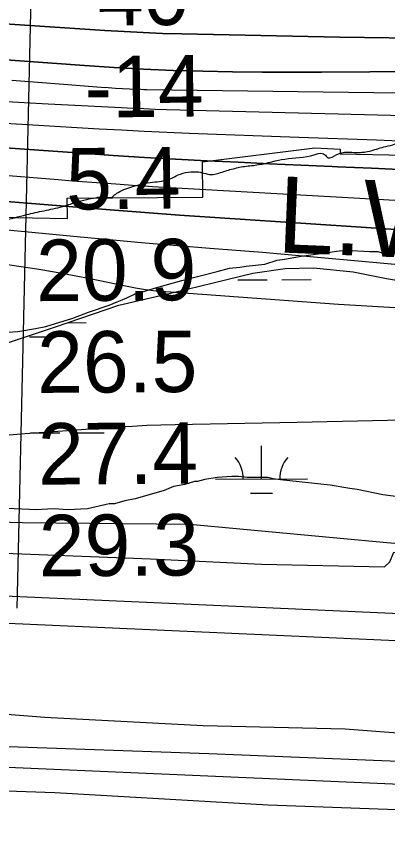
# Model space of a CAD drawing. Extents: x 3329297 to 3367176, y 649250 to 674653.
# Drawn here: x 3334898 to 3335302, y 657903 to 658801 of the extents above; entities that cross this region are included whole.
import ezdxf

# ---------------------------------------------------------------- set-up
doc = ezdxf.new("R2010")
doc.units = 0
for name, color, linetype in [('V-LEVE-TOET', 7, 'Continuous'), ('V-RIVR-EDGE', 7, 'Continuous'), ('V-RIVR-RANG', 7, 'Continuous'), ('V-ROAD-CNTR', 7, 'Continuous'), ('V-RRAP-RVMT', 7, 'Continuous'), ('V-SITE-VEGE', 7, 'Continuous'), ('V-SURV-LINE', 7, 'Continuous'), ('V-TOPO-DPTH', 7, 'Continuous'), ('V-TOPO-MAJR', 7, 'Continuous'), ('V-TOPO-MINR', 7, 'Continuous'), ('V-TOPO-SHOR', 7, 'Continuous'), ('V-TOPO-WATR', 7, 'Continuous'), ('V-TOPO-WATR-IDEN', 7, 'Continuous'), ('V-WETL-SWMP', 7, 'Continuous')]:
    doc.layers.add(name, color=color, linetype=linetype)

msp = doc.modelspace()

# ---------------------------------------------------------------- linework, layer by layer
at = {"layer": 'V-LEVE-TOET'}
for points in [[(3333424.63, 658284.08), (3333476.81, 658281.19), (3333749.42, 658272.3), (3333948.01, 658262.86), (3334211.25, 658250.73), (3334419.86, 658241.85), (3334597.8, 658233.97), (3334838.33, 658218.08), (3335044.27, 658209.9), (3335164.9, 658203.95), (3335298.89, 658201.2), (3335304.94, 658206.46), (3335309.06, 658217.09), (3335518.27, 658202.87)], [(3335958.07, 657989.51), (3335776.1, 657994.77), (3335588.15, 658002.1), (3335408.9, 658012.67), (3335256.34, 658024.29), (3335101.69, 658027.93), (3334929.09, 658037.09), (3334818.5, 658045.6), (3334667.9, 658053.86), (3334510.63, 658061.53), (3334345.37, 658071.29), (3334170.71, 658074.47), (3334012.75, 658080.15), (3333856.17, 658090.48), (3333698.22, 658097.48), (3333552.93, 658103.03), (3333424.89, 658106.3)]]:
    msp.add_lwpolyline(points, dxfattribs=at)
at = {"layer": 'V-RIVR-EDGE'}
msp.add_spline([(3333424.05, 658724.7), (3333474.73, 658717.46), (3333489.07, 658715.87), (3333512.33, 658713.49), (3333530.18, 658715), (3333538.71, 658715.36), (3333547.24, 658714.57), (3333557.71, 658715.7), (3333586.02, 658716.41), (3333612.01, 658718.28), (3333629.86, 658722.12), (3333637.62, 658724.42), (3333647.31, 658724.01), (3333663.6, 658721.26), (3333682.21, 658720.82), (3333707.8, 658719.6), (3333729.52, 658719.93), (3333747.37, 658722.99), (3333760.94, 658721.79), (3333772.95, 658719.82), (3333786.14, 658719.4), (3333801.65, 658718.98), (3333815.21, 658714.68), (3333829.55, 658712.32), (3333853.98, 658710.7), (3333881.51, 658709.09), (3333919.9, 658708.21), (3333933.09, 658708.96), (3333955.19, 658706.58), (3333979.61, 658702.64), (3333997.44, 658699.49), (3334008.3, 658700.63), (3334035.82, 658696.29), (3334058.31, 658693.91), (3334066.07, 658695.06), (3334072.66, 658693.49), (3334092.04, 658688.79), (3334109.87, 658687.19), (3334133.13, 658684.42), (3334151.35, 658681.27), (3334164.92, 658679.69), (3334190.9, 658677.68), (3334204.86, 658676.49), (3334218.42, 658674.13), (3334220.76, 658676.45), (3334226.96, 658676.82), (3334231.62, 658676.81), (3334233.55, 658674.09), (3334237.81, 658672.91), (3334253.71, 658672.87), (3334313.8, 658663.03), (3334340.55, 658660.25), (3334380.48, 658654.72), (3334411.48, 658646.11), (3334421.17, 658643.76), (3334440.16, 658640.23), (3334471.95, 658635.49), (3334501.03, 658634.26), (3334507.24, 658634.24), (3334509.17, 658631.91), (3334513.05, 658629.96), (3334528.94, 658626.05), (3334571.2, 658623.23), (3334582.83, 658621.65), (3334608.04, 658620.81), (3334615.79, 658620.01), (3334621.6, 658617.28), (3334633.23, 658614.93), (3334639.05, 658615.3), (3334646.41, 658615.28), (3334654.94, 658613.71), (3334657.65, 658610.6), (3334668.89, 658607.86), (3334697.18, 658600.03), (3334721.99, 658596.87), (3334746.41, 658594.1), (3334774.71, 658589.76), (3334788.29, 658590.11), (3334793.72, 658591.26), (3334803.41, 658590.85), (3334809.62, 658589.67), (3334816.59, 658585.78), (3334828.61, 658584.97), (3334856.12, 658577.92), (3334862.33, 658577.52), (3334871.63, 658577.89), (3334882.88, 658579.02), (3334909.27, 658585.16), (3334928.28, 658589.38), (3334948.46, 658593.98), (3334962.04, 658598.22), (3334974.85, 658601.67), (3334984.55, 658603.59), (3334993.47, 658604.73), (3335001.61, 658603.94), (3335003.94, 658605.48), (3335009, 658609.35), (3335017.54, 658613.2), (3335043.92, 658620.12), (3335064.1, 658623.56), (3335076.91, 658629.34), (3335088.16, 658631.64), (3335096.31, 658631.62), (3335112.59, 658628.87), (3335118.8, 658630.4), (3335132.38, 658634.64), (3335146.74, 658637.7), (3335161.86, 658639.6), (3335190.58, 658645.74), (3335222.39, 658650.31), (3335231.31, 658651.84), (3335233.64, 658650.67), (3335237.5, 658647.17), (3335247.21, 658650.64), (3335268.93, 658652.91), (3335284.45, 658654.81), (3335300.36, 658659.43), (3335310.45, 658662.12), (3335317.05, 658665.98), (3335327.52, 658665.95), (3335337.6, 658665.54), (3335348.45, 658660.86), (3335353.87, 658658.91), (3335358.52, 658656.96), (3335366.28, 658656.94), (3335378.3, 658655.75), (3335387.6, 658654.95), (3335410.48, 658652.18), (3335422.11, 658652.15), (3335445.77, 658654.8), (3335459.34, 658653.99), (3335474.47, 658652.79), (3335498.1, 658645.75), (3335522.12, 658635.22), (3335524.06, 658634.83), (3335528.73, 658639.86), (3335535.32, 658639.07), (3335541.51, 658635.18), (3335544.99, 658629.74), (3335552.73, 658625.45), (3335563.59, 658624.26), (3335571.34, 658623.47), (3335598.49, 658623.79), (3335622.54, 658624.12), (3335648.9, 658622.5), (3335687.66, 658613.87), (3335732.61, 658599.03), (3335763.22, 658587.32), (3335768.26, 658588.08), (3335771.74, 658585.36), (3335791.88, 658574.06), (3335801.19, 658573.26), (3335807.78, 658573.63), (3335822.89, 658566.23), (3335836.83, 658560.38), (3335873.65, 658551.75), (3335894.2, 658547.82), (3335916.31, 658549.32), (3335929.5, 658552), (3335949.67, 658554.28), (3335958.59, 658554.26), (3335962.85, 658550.76), (3335976.4, 658544.91), (3335989.19, 658542.16), (3335995.01, 658539.82), (3336014.78, 658538.99), (3336032.61, 658534.68), (3336045.79, 658533.1), (3336066.73, 658532.27), (3336083.03, 658535.33), (3336086.53, 658539.2), (3336089.26, 658545.79), (3336091.2, 658548.11), (3336096.25, 658548.88), (3336104.78, 658549.24), (3336126.11, 658548.8), (3336150.54, 658550.29), (3336176.53, 658551.39), (3336187.39, 658554.47), (3336195.94, 658559.49), (3336201.75, 658559.47), (3336210.28, 658556.35), (3336221.52, 658556.71), (3336235.1, 658556.68), (3336248.28, 658557.03), (3336254.1, 658558.57), (3336264.96, 658558.54), (3336271.16, 658553.48), (3336276.57, 658548.82), (3336283.56, 658550.74), (3336285.51, 658553.84), (3336288.62, 658557.71), (3336294.05, 658559.24), (3336313.06, 658561.14), (3336342.15, 658562.62), (3336356.5, 658564.91), (3336366.2, 658566.05), (3336374.35, 658568.35), (3336386.76, 658568.32), (3336402.66, 658568.67), (3336427.86, 658567.83), (3336436.01, 658568.2), (3336451.14, 658570.1), (3336484.9, 658577.78), (3336508.56, 658580.82), (3336517.88, 658587.39), (3336522.54, 658588.15), (3336524.87, 658591.25), (3336527.2, 658593.18), (3336531.86, 658593.17), (3336535.73, 658591.61), (3336537.28, 658588.89), (3336543.87, 658588.88), (3336562.87, 658589.6), (3336584.21, 658591.49), (3336614.46, 658594.13), (3336646.27, 658597.15), (3336666.43, 658596.72), (3336695.13, 658594.32), (3336705.21, 658594.29), (3336734.29, 658593.45), (3336750.58, 658593.02), (3336760.27, 658593.77), (3336768.41, 658592.2), (3336776.93, 658585.97), (3336785.46, 658584.01), (3336796.7, 658582.43), (3336838.19, 658582.33), (3336859.52, 658579.18), (3336880.83, 658572.53), (3336893.24, 658572.5), (3336911.08, 658573.62), (3336926.59, 658573.58), (3336945.21, 658575.47), (3336951.81, 658578.56), (3336960.34, 658578.54), (3336969.64, 658575.8), (3336985.16, 658578.09), (3336999.12, 658578.05), (3337015.8, 658580.34), (3337041.02, 658583.77), (3337061.58, 658586.43), (3337080.98, 658591.43), (3337113.57, 658597.94), (3337142.28, 658602.91), (3337169.45, 658609.43), (3337200.49, 658615.56), (3337235.01, 658620.13), (3337281.96, 658628.93), (3337309.9, 658636.23), (3337337.07, 658645.86), (3337357.25, 658651.63), (3337365.81, 658662.85), (3337368.54, 658669.05), (3337372.81, 658672.53), (3337380.58, 658677.16), (3337399.6, 658684.49), (3337429.1, 658696.82), (3337439.2, 658702.23), (3337449.3, 658709.18), (3337462.89, 658715.35), (3337480.74, 658722.29), (3337488.89, 658723.82), (3337511.41, 658733.85), (3337537.8, 658741.93), (3337559.14, 658747.69), (3337587.46, 658752.27), (3337604.53, 658754.95), (3337622.76, 658756.84), (3337625.48, 658758.39), (3337630.53, 658759.15), (3337640.61, 658759.12), (3337650.68, 658756), (3337655.34, 658755.98), (3337674.74, 658761.37), (3337711.6, 658769.03), (3337723.24, 658772.88), (3337734.87, 658769.75), (3337742.62, 658765.85), (3337750.37, 658765.06), (3337764.33, 658765.41), (3337778.69, 658768.87), (3337789.55, 658769.23), (3337800.81, 658775.02), (3337814.78, 658776.92), (3337832.62, 658779.59), (3337848.13, 658779.94), (3337861.32, 658778.74), (3337867.13, 658775.24), (3337871.01, 658777.17), (3337873.73, 658779.1), (3337884.2, 658779.46), (3337903.6, 658784.46), (3337929.32, 658794.23)], degree=3, dxfattribs=at)
at = {"layer": 'V-RIVR-RANG'}
msp.add_line((3334898.97, 658156.31), (3334925.65, 659316), dxfattribs=at)
at = {"layer": 'V-ROAD-CNTR'}
msp.add_lwpolyline([(3333422.61, 658046.57), (3335843.92, 657941.23)], dxfattribs=at)
at = {"layer": 'V-RRAP-RVMT'}
for p, q in [((3335100.89, 658642.72), (3335222.97, 658658.04)), ((3335222.97, 658658.04), (3335250.86, 658656.35)), ((3335250.86, 658656.35), (3335250.88, 658651.39)), ((3335250.88, 658651.39), (3335321.35, 658650.04)), ((3335101.17, 658604.09), (3335100.89, 658642.72)), ((3334953.62, 658602.95), (3335101.17, 658604.09)), ((3334953.71, 658580.71), (3334953.62, 658602.95)), ((3334797.66, 658583.85), (3334953.71, 658580.71))]:
    msp.add_line(p, q, dxfattribs=at)
at = {"layer": 'V-SITE-VEGE'}
for points in [[(3335116.74, 658523.27), (3335130.3, 658526.59), (3335141.59, 658527.67), (3335148.37, 658528.77), (3335168.7, 658530.93), (3335182.26, 658535.38), (3335190.17, 658536.47), (3335208.24, 658539.77), (3335239.87, 658544.13), (3335246.64, 658545.22), (3335256.81, 658546.3), (3335282.76, 658545.05), (3335291.79, 658545.01), (3335298.55, 658542.72), (3335306.45, 658541.55)], [(3334865.86, 658455.62), (3334899.73, 658457.72), (3334918.93, 658461.02), (3334930.23, 658463.22), (3334959.61, 658472.1), (3334976.58, 658478.8), (3334999.19, 658486.59), (3335018.41, 658494.4), (3335027.46, 658498.87), (3335031.98, 658499.98), (3335051.2, 658505.53), (3335078.32, 658513.3), (3335116.74, 658523.27)], [(3335322.11, 658276.24), (3335297.29, 658279.74), (3335269.1, 658285.52), (3335261.21, 658286.69), (3335239.78, 658290.18), (3335185.63, 658296.08), (3335177.74, 658297.25), (3335172.1, 658298.4), (3335149.53, 658298.51), (3335140.5, 658299.68), (3335132.6, 658299.72), (3335116.8, 658298.67), (3335103.24, 658296.47), (3335095.33, 658294.26), (3335091.95, 658294.27), (3335081.77, 658290.94), (3335069.35, 658288.73), (3335059.17, 658284.27), (3335027.52, 658275.39), (3335016.22, 658273.19), (3335004.92, 658269.86), (3334999.28, 658269.88), (3334975.55, 658264.35), (3334954.1, 658263.33), (3334939.43, 658264.53), (3334919.11, 658263.5), (3334912.34, 658263.53), (3334887.52, 658264.78)]]:
    msp.add_lwpolyline(points, dxfattribs=at)
at = {"layer": 'V-SURV-LINE'}
for points in [[(3333424.71, 658235.03), (3336500.17, 658097.33)], [(3336498.83, 658067.36), (3333424.75, 658205)]]:
    msp.add_lwpolyline(points, dxfattribs=at)
at = {"layer": 'V-TOPO-DPTH'}
for points in [[(3337123.03, 658764.54), (3336302.7, 658787.77), (3336275.13, 658787.05), (3336247.56, 658786.4), (3336219.99, 658785.85), (3336192.42, 658785.37), (3335678.72, 658777.45), (3335571.65, 658776.38), (3335464.59, 658776.08), (3335357.53, 658776.94), (3335250.48, 658778.58), (3335078.33, 658782.14), (3335057.35, 658782.72), (3335036.39, 658783.49), (3335015.43, 658784.56), (3334994.49, 658785.82), (3334879.83, 658793.5)], [(3337123.03, 658764.54), (3336302.7, 658787.77), (3336275.13, 658787.05), (3336247.56, 658786.4), (3336219.99, 658785.85), (3336192.42, 658785.37), (3335678.72, 658777.45), (3335571.65, 658776.38), (3335464.59, 658776.08), (3335357.53, 658776.94), (3335250.48, 658778.58), (3335078.33, 658782.14), (3335057.35, 658782.72), (3335036.39, 658783.49), (3335015.43, 658784.56), (3334994.49, 658785.82), (3334879.83, 658793.5)], [(3337127.53, 658739.26), (3336189.79, 658733.67), (3336157.06, 658735.74), (3336108.04, 658738.39), (3336059, 658740.45), (3336009.93, 658741.64), (3335960.84, 658742.23), (3335833.71, 658742.65), (3335722.41, 658742.82), (3335611.11, 658742.74), (3335499.81, 658742.29), (3335388.51, 658741.59), (3335230.53, 658740.33), (3335198.22, 658740.22), (3335165.92, 658740.33), (3335133.61, 658740.73), (3335101.31, 658741.34), (3335069.03, 658742.35), (3335036.75, 658743.66), (3335004.5, 658745.45), (3334972.27, 658747.56), (3334595.12, 658774.96)], [(3334595.12, 658774.96), (3334972.27, 658747.56), (3335004.5, 658745.45), (3335036.75, 658743.66), (3335069.03, 658742.35), (3335101.31, 658741.34), (3335133.61, 658740.73), (3335165.92, 658740.33), (3335198.22, 658740.22), (3335230.53, 658740.33), (3335388.51, 658741.59), (3335499.81, 658742.29), (3335611.11, 658742.74), (3335722.41, 658742.82), (3335833.71, 658742.65), (3335960.84, 658742.23), (3336009.93, 658741.64), (3336059, 658740.45), (3336108.04, 658738.39), (3336157.06, 658735.74), (3336189.79, 658733.67), (3337127.53, 658739.26)], [(3334880.79, 658708.66), (3334932.88, 658705.77), (3335012.61, 658701.72), (3335024.85, 658701.14), (3335037.09, 658700.63), (3335049.34, 658700.2), (3335061.58, 658699.84), (3335306.06, 658693.49), (3335440.53, 658689.52), (3335574.97, 658684.92), (3335709.38, 658679.36), (3335843.76, 658673.18), (3336078.58, 658661.53)], [(3334880.79, 658708.66), (3334932.88, 658705.77), (3335012.61, 658701.72), (3335024.85, 658701.14), (3335037.09, 658700.63), (3335049.34, 658700.2), (3335061.58, 658699.84), (3335306.06, 658693.49), (3335440.53, 658689.52), (3335574.97, 658684.92), (3335709.38, 658679.36), (3335843.76, 658673.18), (3336078.58, 658661.53)], [(3335996.42, 658593.9), (3335884.06, 658601.11), (3335771.69, 658608.13), (3335659.31, 658614.86), (3335546.91, 658621.4), (3335396.2, 658629.98), (3335359.14, 658632.02), (3335322.08, 658633.94), (3335285.01, 658635.72), (3335247.93, 658637.38), (3335241.9, 658637.64), (3335207.84, 658639.13), (3335173.78, 658640.66), (3335139.72, 658642.25), (3335105.66, 658643.87), (3335071.62, 658645.63), (3335037.58, 658647.54), (3335003.55, 658649.67), (3334969.53, 658651.94), (3334626.16, 658675.99)], [(3334626.16, 658675.99), (3334969.53, 658651.94), (3335003.55, 658649.67), (3335037.58, 658647.54), (3335071.62, 658645.63), (3335105.66, 658643.87), (3335139.72, 658642.25), (3335173.78, 658640.66), (3335207.84, 658639.13), (3335241.9, 658637.64), (3335247.93, 658637.38), (3335285.01, 658635.72), (3335322.08, 658633.94), (3335359.14, 658632.02), (3335396.2, 658629.98), (3335546.91, 658621.4), (3335659.31, 658614.86), (3335771.69, 658608.13), (3335884.06, 658601.11), (3335996.42, 658593.9)], [(3335979.47, 658525.46), (3335907.54, 658526.64), (3335835.67, 658529.63), (3335763.83, 658533.83), (3335739.45, 658535.56), (3335679.83, 658539.92), (3335620.23, 658544.44), (3335560.65, 658549.19), (3335501.07, 658554.1), (3335441.5, 658558.97), (3335381.91, 658563.64), (3335322.3, 658568), (3335262.67, 658572.15), (3335075.76, 658584.7), (3335056.93, 658586), (3335038.09, 658587.36), (3335019.26, 658588.79), (3335000.44, 658590.28), (3334910.23, 658597.6), (3334846.31, 658602.76)]]:
    msp.add_lwpolyline(points, dxfattribs=at)
at = {"layer": 'V-TOPO-MAJR'}
msp.add_lwpolyline([(3334841.6, 658340.97), (3334907.7, 658346.53), (3335009.3, 658353.71), (3335024.71, 658354.68), (3335040.13, 658355.49), (3335055.56, 658356.06), (3335070.99, 658356.47), (3335204.04, 658358.98), (3335286.01, 658360.61), (3335367.97, 658362.35), (3335449.93, 658364.24), (3335531.89, 658366.24), (3336240.94, 658384.23), (3336270.75, 658385.21), (3336300.54, 658386.49), (3336330.31, 658388.22), (3336360.07, 658390.25), (3336389.78, 658392.79), (3336419.46, 658395.7), (3336449.07, 658399.18), (3336478.64, 658403.02), (3337100.69, 658489.89)], dxfattribs=at)
at = {"layer": 'V-TOPO-MINR'}
for points in [[(3334879.83, 658793.5), (3334994.49, 658785.82), (3335015.43, 658784.56), (3335036.39, 658783.49), (3335057.35, 658782.72), (3335078.33, 658782.14), (3335250.48, 658778.58), (3335357.53, 658776.94), (3335464.59, 658776.08), (3335571.65, 658776.38), (3335678.72, 658777.45), (3336192.42, 658785.37), (3336219.99, 658785.85), (3336247.56, 658786.4), (3336275.13, 658787.05), (3336302.7, 658787.77), (3337123.03, 658764.54)], [(3334595.12, 658774.96), (3334972.27, 658747.56), (3335004.5, 658745.45), (3335036.75, 658743.66), (3335069.03, 658742.35), (3335101.31, 658741.34), (3335133.61, 658740.73), (3335165.92, 658740.33), (3335198.22, 658740.22), (3335230.53, 658740.33), (3335388.51, 658741.59), (3335499.81, 658742.29), (3335611.11, 658742.74), (3335722.41, 658742.82), (3335833.71, 658742.65), (3335960.84, 658742.23), (3336009.93, 658741.64), (3336059, 658740.45), (3336108.04, 658738.39), (3336157.06, 658735.74), (3336189.79, 658733.67), (3337127.53, 658739.26)], [(3334893.33, 658731.62), (3334921.5, 658729.45), (3334949.67, 658727.28), (3334990.58, 658724.11), (3334998.29, 658723.55), (3335006.01, 658723.05), (3335013.73, 658722.63), (3335021.45, 658722.26), (3335033.54, 658721.76), (3335036.9, 658721.64), (3335040.27, 658721.57), (3335561.64, 658714.73), (3335678.2, 658712.53), (3335794.74, 658709.46), (3335911.23, 658705.07), (3336027.69, 658699.8), (3336237.18, 658689.13), (3336248.87, 658688.49), (3336260.57, 658687.8), (3336272.26, 658687.03), (3336283.94, 658686.2), (3336310.93, 658684.19), (3336324.22, 658683.25), (3337109.59, 658723.16)], [(3334880.79, 658708.66), (3334932.88, 658705.77), (3335012.61, 658701.72), (3335024.85, 658701.14), (3335037.09, 658700.63), (3335049.34, 658700.2), (3335061.58, 658699.84), (3335306.06, 658693.49), (3335440.53, 658689.52), (3335574.97, 658684.92), (3335709.38, 658679.36), (3335843.76, 658673.18), (3336078.58, 658661.53)], [(3334843.46, 658687.48), (3334988.28, 658678.81), (3335012.8, 658677.43), (3335037.32, 658676.16), (3335061.84, 658675.06), (3335086.38, 658674.08), (3335205.85, 658669.7), (3335290.12, 658666.5), (3335374.38, 658663.13), (3335458.63, 658659.52), (3335542.87, 658655.74), (3335600.28, 658653.09), (3335663.03, 658650.05), (3335725.78, 658646.82), (3335788.52, 658643.32), (3335851.24, 658639.63), (3335913.96, 658635.81)], [(3334871.15, 658629.16), (3334943.69, 658623.33), (3334959.37, 658622.09), (3334975.06, 658620.89), (3334990.75, 658619.72), (3335006.44, 658618.59), (3335029.23, 658616.98), (3335033.53, 658616.68), (3335037.83, 658616.4), (3335042.13, 658616.14), (3335046.43, 658615.88), (3335368.85, 658597.63), (3335471.29, 658591.57), (3335573.7, 658585.16), (3335676.08, 658578.25), (3335778.44, 658570.98), (3335915.12, 658560.94)], [(3334846.31, 658602.76), (3334910.23, 658597.6), (3335000.44, 658590.28), (3335019.26, 658588.79), (3335038.09, 658587.36), (3335056.93, 658586), (3335075.76, 658584.7), (3335262.67, 658572.15), (3335322.3, 658568), (3335381.91, 658563.64), (3335441.5, 658558.97), (3335501.07, 658554.1), (3335560.65, 658549.19), (3335620.23, 658544.44), (3335679.83, 658539.92), (3335739.45, 658535.56), (3335763.83, 658533.83), (3335835.67, 658529.63), (3335907.54, 658526.64), (3335979.47, 658525.46)], [(3334819.71, 658575.03), (3334967.87, 658560.9), (3335003.13, 658557.62), (3335038.4, 658554.47), (3335073.68, 658551.49), (3335108.98, 658548.64), (3335142.08, 658546.04), (3335166.11, 658544.1), (3335190.14, 658542.07), (3335214.16, 658539.92), (3335238.17, 658537.69), (3335262.18, 658535.44), (3335286.19, 658533.26), (3335310.22, 658531.18), (3335334.25, 658529.16), (3335490.93, 658516.32), (3335593.36, 658509.33), (3335695.86, 658504.2), (3335798.46, 658501.87), (3335901.12, 658501.39), (3336223.55, 658504.29)], [(3334881.4, 658531.81), (3334900.9, 658528.99), (3334920.38, 658525.98), (3334939.81, 658522.7), (3334959.21, 658519.23), (3334978.55, 658515.45), (3334997.85, 658511.49), (3335017.06, 658507.38), (3335027.98, 658505.29), (3335038.93, 658503.5), (3335049.96, 658502.17), (3335061.02, 658501.15), (3335248.87, 658487.69), (3335353.92, 658481.44), (3335459.04, 658476.89), (3335564.23, 658474.88), (3335669.47, 658474.57), (3336252.6, 658479.89)]]:
    msp.add_lwpolyline(points, dxfattribs=at)
at = {"layer": 'V-TOPO-SHOR'}
for points in [[(3333462.61, 658069.31), (3333547.91, 658065.45), (3333666.3, 658062.83), (3333939.08, 658049.73), (3334145.85, 658038.7), (3334389.4, 658029.31), (3334654.02, 658016.97), (3334879.17, 658005.74), (3335107.76, 657997.87), (3335394.83, 657985.98), (3335550.63, 657980.92), (3335756.72, 657969.21), (3335939.05, 657962.51), (3336041.03, 657952.58), (3336136.14, 657936.6), (3336224.38, 657914.57), (3336309.59, 657887.37)], [(3334783.11, 657960.79), (3334939.95, 657955.03), (3335172.44, 657941.65), (3335362.01, 657934.86), (3335536.55, 657925.51), (3335750.66, 657916.42), (3335927.25, 657907.04)]]:
    msp.add_lwpolyline(points, dxfattribs=at)
at = {"layer": 'V-TOPO-WATR'}
msp.add_lwpolyline([(3334626.16, 658675.99), (3334969.53, 658651.94), (3335003.55, 658649.67), (3335037.58, 658647.54), (3335071.62, 658645.63), (3335105.66, 658643.87), (3335139.72, 658642.25), (3335173.78, 658640.66), (3335207.84, 658639.13), (3335241.9, 658637.64), (3335247.93, 658637.38), (3335285.01, 658635.72), (3335322.08, 658633.94), (3335359.14, 658632.02), (3335396.2, 658629.98), (3335546.91, 658621.4), (3335659.31, 658614.86), (3335771.69, 658608.13), (3335884.06, 658601.11), (3335996.42, 658593.9)], dxfattribs=at)
at = {"layer": 'V-WETL-SWMP'}
for p, q in [((3335190.77, 658526.24), (3335221.76, 658527.25)), ((3335221.76, 658527.25), (3335264.81, 658522.76)), ((3335112.49, 658510.9), (3335155.7, 658521.22)), ((3335155.7, 658521.22), (3335190.77, 658526.24)), ((3335264.81, 658522.76), (3335301.1, 658515.64)), ((3335070.63, 658500.57), (3335112.49, 658510.9)), ((3335139.27, 658514.11), (3335171.27, 658514.17)), ((3335187.27, 658514.2), (3335219.27, 658514.26)), ((3335301.1, 658515.64), (3335341.43, 658508.48)), ((3335009.87, 658486.4), (3335070.63, 658500.57)), ((3334940.93, 658462.89), (3335009.87, 658486.4)), ((3334953.96, 658467.33), (3334974.29, 658467.37)), ((3334874.7, 658440.7), (3334940.93, 658462.89)), ((3334912.32, 658451.82), (3334936.32, 658451.87)), ((3334913.68, 658347.18), (3334945.68, 658347.24)), ((3334961.68, 658347.27), (3334993.68, 658347.34)), ((3335165.09, 658296.92), (3335165.02, 658332.92)), ((3335115.09, 658296.82), (3335215.09, 658297.01)), ((3335153.12, 658281.46), (3335177.12, 658281.51)), ((3334904.94, 658249.12), (3334656.67, 658257.15)), ((3335087.13, 658247.19), (3334904.94, 658249.12)), ((3335301.53, 658227.37), (3335087.13, 658247.19)), ((3335497.08, 658211.8), (3335301.53, 658227.37))]:
    msp.add_line(p, q, dxfattribs=at)
for centre, start, end in [((3335109.85, 658297.29), 359.33648, 40.88014), ((3335220.33, 658297.5), 139.33648, 180.88013)]:
    msp.add_arc(centre, 35.25, start, end, dxfattribs=at)

# ---------------------------------------------------------------- texts
at = {"layer": 'V-RIVR-RANG'}
for s, rotation, p in [('-40', 0.64425, (3334957.24, 658790.59)), ('-14', 0.64425, (3334972.89, 658690.76)), ('5.4', 0.64425, (3334952.67, 658590.53)), ('20.9', 0.35833, (3334919.88, 658490.74)), ('26.5', 0.35833, (3334921.02, 658390.75)), ('27.4', 0.35833, (3334921.89, 658290.75)), ('29.3', 0.35833, (3334922.77, 658190.76))]:
    msp.add_text(s, height=67, rotation=rotation, dxfattribs=at).set_placement(p)
at = {"layer": 'V-TOPO-WATR-IDEN'}
msp.add_text('L.W.R.P.', height=83, rotation=357.63261, dxfattribs=at).set_placement((3335181.31, 658544.04))

doc.saveas('drawing.dxf')
